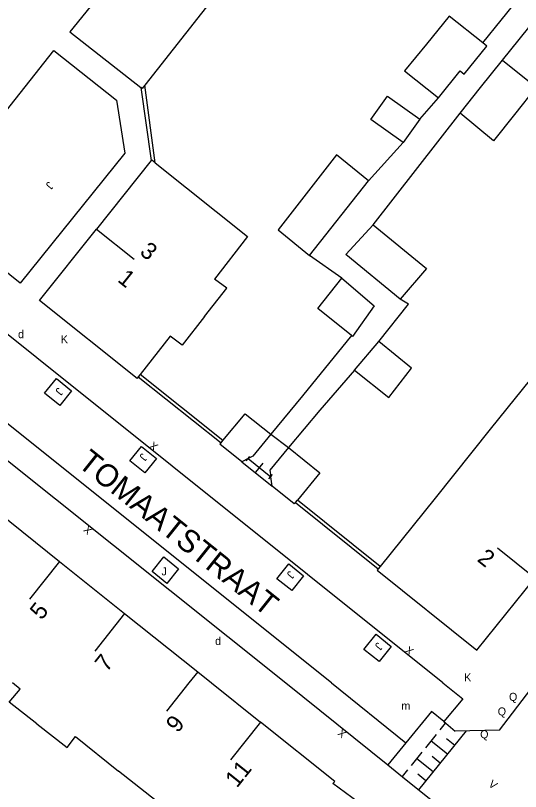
# Model space of a CAD drawing. Extents: x 134999 to 136502, y 457398 to 459002.
# Drawn here: x 135341.41 to 135372.94, y 457793.22 to 457841.67 of the extents above; entities that cross this region are included whole.
import ezdxf

# ---------------------------------------------------------------- set-up
doc = ezdxf.new("R2010")
doc.units = 0
for name, color, linetype in [('RI_DGTB_15', 7, 'Continuous'), ('RI_DGTB_23', 7, 'Continuous'), ('RI_DGTB_29', 7, 'Continuous'), ('RI_DGTB_30', 7, 'Continuous'), ('RI_DGTB_31', 7, 'Continuous'), ('RI_DGTB_35', 7, 'Continuous'), ('RI_DGTB_36', 7, 'Continuous'), ('RI_DGTB_37', 7, 'Continuous'), ('RI_DGTB_4', 7, 'Continuous'), ('RI_DGTB_43', 7, 'Continuous'), ('RI_DGTB_48', 7, 'Continuous'), ('RI_DGTB_5', 7, 'Continuous'), ('RI_DGTB_53', 7, 'Continuous'), ('RI_DGTB_54', 7, 'Continuous'), ('RI_DGTB_6', 7, 'Continuous'), ('RI_DGTB_7', 7, 'Continuous')]:
    doc.layers.add(name, color=color, linetype=linetype)

msp = doc.modelspace()

# ---------------------------------------------------------------- linework, layer by layer
at = {"layer": 'RI_DGTB_15'}
for p, q in [((135346.469, 457828.337), (135348.813, 457826.464)), ((135346.469, 457828.337), (135348.813, 457826.464)), ((135373.839, 457806.545), (135371.499, 457808.422)), ((135373.839, 457806.545), (135371.499, 457808.422)), ((135344.159, 457807.579), (135342.293, 457805.231)), ((135344.159, 457807.579), (135342.293, 457805.231)), ((135348.221, 457804.331), (135346.355, 457801.983)), ((135348.221, 457804.331), (135346.355, 457801.983)), ((135352.793, 457800.688), (135352.245, 457800)), ((135352.793, 457800.688), (135352.245, 457800)), ((135352.245, 457800), (135350.83, 457798.228)), ((135356.716, 457797.543), (135354.845, 457795.199))]:
    msp.add_line(p, q, dxfattribs=at)
at = {"layer": 'RI_DGTB_23'}
msp.add_line((135355.539, 457813.811), (135357.44, 457812.288), dxfattribs=at)
msp.add_line((135355.539, 457813.811), (135357.44, 457812.288), dxfattribs=at)
at = {"layer": 'RI_DGTB_31'}
for p, q in [((135367.931, 457797.059), (135368.267, 457797.475)), ((135366.595, 457793.329), (135369.565, 457797.005)), ((135367.035, 457795.95), (135367.707, 457796.782)), ((135368.386, 457795.546), (135367.371, 457796.366)), ((135368.834, 457796.1), (135368.327, 457796.51)), ((135366.139, 457794.84), (135366.811, 457795.672)), ((135367.49, 457794.436), (135366.475, 457795.256)), ((135367.938, 457794.991), (135367.431, 457795.401)), ((135365.579, 457794.147), (135365.915, 457794.563)), ((135367.042, 457793.882), (135366.535, 457794.292))]:
    msp.add_line(p, q, dxfattribs=at)
for points in [[(135343.226, 457818.083), (135343.963, 457819.005), (135344.915, 457818.244), (135344.178, 457817.322)], [(135343.226, 457818.083), (135343.963, 457819.005), (135344.915, 457818.244), (135344.178, 457817.322)], [(135348.555, 457813.858), (135349.273, 457814.757), (135350.209, 457814.009), (135349.491, 457813.11)], [(135348.555, 457813.858), (135349.273, 457814.757), (135350.209, 457814.009), (135349.491, 457813.11)], [(135349.941, 457806.955), (135350.665, 457807.862), (135351.595, 457807.119), (135350.871, 457806.212)], [(135349.941, 457806.955), (135350.665, 457807.862), (135351.595, 457807.119), (135350.871, 457806.212)], [(135357.731, 457806.505), (135358.474, 457807.435), (135359.403, 457806.692), (135358.66, 457805.762)], [(135357.731, 457806.505), (135358.474, 457807.435), (135359.403, 457806.692), (135358.66, 457805.762)], [(135363.166, 457802.093), (135363.922, 457803.038), (135364.867, 457802.282), (135364.111, 457801.337)], [(135363.166, 457802.093), (135363.922, 457803.038), (135364.867, 457802.282), (135364.111, 457801.337)]]:
    msp.add_lwpolyline(points, close=True, dxfattribs=at)
at = {"layer": 'RI_DGTB_4'}
for p, q in [((135354.061, 457843.14), (135349.485, 457837.321)), ((135349.889, 457832.616), (135346.469, 457828.337)), ((135349.889, 457832.616), (135346.469, 457828.337)), ((135351.065, 457821.651), (135349.2, 457819.255)), ((135351.065, 457821.651), (135349.2, 457819.255)), ((135349.2, 457819.255), (135349.081, 457819.102)), ((135349.2, 457819.255), (135349.081, 457819.102)), ((135339.674, 457811.167), (135344.161, 457807.581)), ((135339.674, 457811.167), (135344.161, 457807.581)), ((135344.161, 457807.581), (135348.224, 457804.334)), ((135344.161, 457807.581), (135348.224, 457804.334)), ((135348.224, 457804.334), (135352.79, 457800.685)), ((135348.224, 457804.334), (135352.79, 457800.685)), ((135352.79, 457800.685), (135353.647, 457800)), ((135352.79, 457800.685), (135353.647, 457800)), ((135353.647, 457800), (135356.718, 457797.546))]:
    msp.add_line(p, q, dxfattribs=at)
for points in [[(135349.697, 457846.698), (135344.809, 457840.663), (135349.233, 457837.181)], [(135349.485, 457837.321), (135349.321, 457837.112), (135349.233, 457837.181)], [(135350.134, 457832.475), (135349.916, 457832.649), (135349.889, 457832.616)], [(135350.134, 457832.475), (135349.916, 457832.649), (135349.889, 457832.616)], [(135350.134, 457832.475), (135355.903, 457827.871), (135353.839, 457825.218)], [(135350.134, 457832.475), (135355.903, 457827.871), (135353.839, 457825.218)], [(135349.081, 457819.102), (135349, 457818.998), (135342.907, 457823.881), (135346.469, 457828.337)], [(135349.081, 457819.102), (135349, 457818.998), (135342.907, 457823.881), (135346.469, 457828.337)], [(135363.986, 457807.032), (135370.226, 457802.041), (135373.837, 457806.546)], [(135363.986, 457807.032), (135370.226, 457802.041), (135373.837, 457806.546)], [(135361.5, 457788.617), (135363.351, 457790.897), (135363.198, 457792.262), (135361.222, 457793.718), (135361.349, 457793.845), (135356.718, 457797.546)]]:
    msp.add_lwpolyline(points, dxfattribs=at)
at = {"layer": 'RI_DGTB_48'}
for p, q in [((135355.822, 457813.865), (135356.048, 457814.147)), ((135355.822, 457813.865), (135356.048, 457814.147)), ((135355.935, 457814.006), (135357.348, 457812.874)), ((135355.935, 457814.006), (135357.348, 457812.874)), ((135355.935, 457814.006), (135357.348, 457812.874)), ((135355.935, 457814.006), (135357.348, 457812.874)), ((135356.415, 457813.157), (135356.868, 457813.723)), ((135356.415, 457813.157), (135356.868, 457813.723)), ((135357.235, 457812.733), (135357.461, 457813.015)), ((135357.235, 457812.733), (135357.461, 457813.015))]:
    msp.add_line(p, q, dxfattribs=at)
at = {"layer": 'RI_DGTB_5'}
for p, q in [((135374.492, 457820.127), (135371.05, 457815.836)), ((135374.492, 457820.127), (135371.05, 457815.836)), ((135371.05, 457815.836), (135367.606, 457811.544)), ((135371.05, 457815.836), (135367.606, 457811.544)), ((135367.606, 457811.544), (135364.177, 457807.27)), ((135367.606, 457811.544), (135364.177, 457807.27)), ((135364.177, 457807.27), (135364.06, 457807.125)), ((135364.177, 457807.27), (135364.06, 457807.125)), ((135364.06, 457807.125), (135363.986, 457807.032)), ((135364.06, 457807.125), (135363.986, 457807.032))]:
    msp.add_line(p, q, dxfattribs=at)
for points in [[(135353.218, 457822.882), (135354.612, 457824.65), (135353.839, 457825.218)], [(135353.218, 457822.882), (135354.612, 457824.65), (135353.839, 457825.218)], [(135353.218, 457822.882), (135351.81, 457821.098), (135351.065, 457821.651)], [(135353.218, 457822.882), (135351.81, 457821.098), (135351.065, 457821.651)], [(135342.748, 457797.444), (135341.015, 457798.796), (135341.708, 457799.616), (135341.228, 457800)], [(135342.748, 457797.444), (135344.634, 457795.972), (135345.162, 457796.645), (135347.85, 457794.495)], [(135351.238, 457790.679), (135349.64, 457791.9), (135350.187, 457792.626), (135347.85, 457794.495)]]:
    msp.add_lwpolyline(points, dxfattribs=at)
at = {"layer": 'RI_DGTB_53'}
msp.add_line((135361.142, 457800), (135365.792, 457796.264), dxfattribs=at)
msp.add_lwpolyline([(135361.149, 457800), (135340.114, 457816.81), (135338.999, 457815.415)], dxfattribs=at)
msp.add_lwpolyline([(135361.149, 457800), (135340.114, 457816.81), (135338.999, 457815.415)], dxfattribs=at)
at = {"layer": 'RI_DGTB_54'}
for p, q in [((135370.583, 457839.961), (135374.666, 457845.018)), ((135350.134, 457832.475), (135349.485, 457837.321)), ((135349.233, 457837.181), (135349.889, 457832.616)), ((135366.666, 457835.21), (135367.833, 457836.534)), ((135366.666, 457835.21), (135367.833, 457836.534)), ((135363.745, 457828.606), (135369.176, 457835.585)), ((135363.745, 457828.606), (135369.176, 457835.585)), ((135363.457, 457831.341), (135365.615, 457833.734)), ((135363.457, 457831.341), (135365.615, 457833.734)), ((135361.783, 457825.262), (135359.765, 457826.686)), ((135361.783, 457825.262), (135359.765, 457826.686)), ((135349.081, 457819.102), (135354.247, 457814.997)), ((135349.081, 457819.102), (135354.247, 457814.997)), ((135354.354, 457815.126), (135349.2, 457819.255)), ((135354.354, 457815.126), (135349.2, 457819.255)), ((135338.999, 457815.415), (135358.291, 457800)), ((135338.999, 457815.415), (135358.291, 457800)), ((135358.899, 457811.267), (135364.06, 457807.125)), ((135358.899, 457811.267), (135364.06, 457807.125)), ((135364.177, 457807.27), (135359.013, 457811.407)), ((135364.177, 457807.27), (135359.013, 457811.407)), ((135358.291, 457800), (135364.663, 457794.881)), ((135371.639, 457797.057), (135373.589, 457799.605)), ((135371.639, 457797.057), (135368.863, 457796.988)), ((135365.792, 457796.264), (135364.663, 457794.881))]:
    msp.add_line(p, q, dxfattribs=at)
for points in [[(135371.83, 457838.886), (135373.981, 457841.574)], [(135336.849, 457828.858), (135336.942, 457830.815), (135343.802, 457839.481), (135347.711, 457836.395), (135348.249, 457833.08), (135341.698, 457824.965), (135336.849, 457828.858)], [(135368.102, 457800), (135334.271, 457827.065), (135333.852, 457826.605)], [(135368.102, 457800), (135334.271, 457827.065), (135333.852, 457826.605)], [(135364.091, 457821.323), (135365.951, 457823.641), (135365.439, 457823.965)], [(135364.091, 457821.323), (135365.951, 457823.641), (135365.439, 457823.965)], [(135362.387, 457821.696), (135359.339, 457817.927), (135357.357, 457815.526)], [(135362.387, 457821.696), (135359.339, 457817.927), (135357.357, 457815.526)], [(135362.588, 457819.537), (135360.415, 457817.034), (135358.454, 457814.691)], [(135362.588, 457819.537), (135360.415, 457817.034), (135358.454, 457814.691)], [(135368.102, 457800), (135369.335, 457799.014), (135368.161, 457797.582)], [(135368.161, 457797.582), (135367.387, 457798.215), (135365.792, 457796.264)], [(135368.161, 457797.582), (135368.279, 457797.482)], [(135368.279, 457797.482), (135368.863, 457796.988)], [(135364.663, 457794.881), (135365.582, 457794.143)], [(135365.582, 457794.143), (135372.361, 457788.697)]]:
    msp.add_lwpolyline(points, dxfattribs=at)
at = {"layer": 'RI_DGTB_6'}
for p, q in [((135371.83, 457838.886), (135373.923, 457837.202)), ((135359.765, 457826.686), (135363.457, 457831.341)), ((135359.765, 457826.686), (135363.457, 457831.341)), ((135362.588, 457819.537), (135364.091, 457821.323)), ((135362.588, 457819.537), (135364.091, 457821.323)), ((135354.247, 457814.997), (135354.354, 457815.126)), ((135354.247, 457814.997), (135354.354, 457815.126)), ((135358.899, 457811.267), (135359.013, 457811.407)), ((135358.899, 457811.267), (135359.013, 457811.407))]:
    msp.add_line(p, q, dxfattribs=at)
for points in [[(135368.5, 457841.634), (135367.078, 457839.894)], [(135370.583, 457839.961), (135368.5, 457841.634)], [(135367.078, 457839.894), (135365.708, 457838.217), (135367.833, 457836.534)], [(135369.173, 457838.214), (135369.43, 457838.008), (135370.837, 457839.757), (135370.583, 457839.961)], [(135370.457, 457837.182), (135371.83, 457838.886)], [(135367.833, 457836.534), (135369.173, 457838.214)], [(135369.176, 457835.585), (135370.457, 457837.182)], [(135373.923, 457837.202), (135372.563, 457835.494)], [(135365.615, 457833.734), (135363.598, 457835.171), (135364.65, 457836.647)], [(135365.615, 457833.734), (135363.598, 457835.171), (135364.65, 457836.647)], [(135364.65, 457836.647), (135366.666, 457835.21)], [(135364.65, 457836.647), (135366.666, 457835.21)], [(135372.563, 457835.494), (135371.256, 457833.853), (135369.176, 457835.585)], [(135372.563, 457835.494), (135371.256, 457833.853), (135369.176, 457835.585)], [(135366.666, 457835.21), (135365.615, 457833.734)], [(135366.666, 457835.21), (135365.615, 457833.734)], [(135363.457, 457831.341), (135361.458, 457832.979), (135357.816, 457828.284), (135359.765, 457826.686)], [(135363.457, 457831.341), (135361.458, 457832.979), (135357.816, 457828.284), (135359.765, 457826.686)], [(135365.439, 457823.965), (135362.042, 457826.742), (135363.745, 457828.606)], [(135365.439, 457823.965), (135362.042, 457826.742), (135363.745, 457828.606)], [(135363.745, 457828.606), (135367.081, 457825.879), (135365.439, 457823.965)], [(135363.745, 457828.606), (135367.081, 457825.879), (135365.439, 457823.965)], [(135362.387, 457821.696), (135360.287, 457823.386), (135361.783, 457825.262)], [(135362.387, 457821.696), (135360.287, 457823.386), (135361.783, 457825.262)], [(135361.783, 457825.262), (135363.804, 457823.545), (135362.464, 457821.635), (135362.387, 457821.696)], [(135361.783, 457825.262), (135363.804, 457823.545), (135362.464, 457821.635), (135362.387, 457821.696)], [(135362.588, 457819.537), (135364.725, 457817.817), (135366.146, 457819.648), (135364.091, 457821.323)], [(135362.588, 457819.537), (135364.725, 457817.817), (135366.146, 457819.648), (135364.091, 457821.323)], [(135354.354, 457815.126), (135355.748, 457816.807), (135357.357, 457815.526)], [(135354.354, 457815.126), (135355.748, 457816.807), (135357.357, 457815.526)], [(135357.357, 457815.526), (135356.233, 457814.152), (135355.935, 457814.006)], [(135357.357, 457815.526), (135356.233, 457814.152), (135355.935, 457814.006)], [(135355.539, 457813.811), (135354.177, 457814.913), (135354.247, 457814.997)], [(135355.539, 457813.811), (135354.177, 457814.913), (135354.247, 457814.997)], [(135358.454, 457814.691), (135357.285, 457813.273), (135357.348, 457812.874)], [(135358.454, 457814.691), (135357.285, 457813.273), (135357.348, 457812.874)], [(135358.454, 457814.691), (135360.419, 457813.123), (135359.013, 457811.407)], [(135358.454, 457814.691), (135360.419, 457813.123), (135359.013, 457811.407)], [(135355.935, 457814.006), (135355.539, 457813.811)], [(135355.935, 457814.006), (135355.539, 457813.811)], [(135357.44, 457812.288), (135357.348, 457812.874)], [(135357.44, 457812.288), (135357.348, 457812.874)], [(135358.899, 457811.267), (135358.822, 457811.173), (135357.44, 457812.288)], [(135358.899, 457811.267), (135358.822, 457811.173), (135357.44, 457812.288)]]:
    msp.add_lwpolyline(points, dxfattribs=at)
at = {"layer": 'RI_DGTB_7'}
for points in [[(135357.357, 457815.526), (135358.454, 457814.691)], [(135357.357, 457815.526), (135358.454, 457814.691)], [(135355.539, 457813.811), (135357.44, 457812.288)], [(135355.539, 457813.811), (135357.44, 457812.288)]]:
    msp.add_lwpolyline(points, dxfattribs=at)

# ---------------------------------------------------------------- texts
at = {"layer": 'RI_DGTB_29'}
for height, p in [(0.499, (135341.57, 457821.525)), (0.499, (135341.57, 457821.525)), (0.5, (135353.873, 457802.367)), (0.5, (135353.873, 457802.367))]:
    msp.add_text('d', height=height, dxfattribs=at).set_placement(p)
at = {"layer": 'RI_DGTB_30'}
for p in [(135344.241, 457821.21), (135344.241, 457821.21), (135369.425, 457800.096), (135369.425, 457800.096)]:
    msp.add_text('K', height=0.5, dxfattribs=at).set_placement(p)
for s, rotation, p in [('X', 321.3711, (135349.703, 457814.72)), ('X', 321.3711, (135349.703, 457814.72)), ('X', 136.3013, (135346.273, 457809.576)), ('X', 136.3013, (135346.273, 457809.576)), ('X', 321.3305, (135365.665, 457801.95)), ('X', 321.3305, (135365.665, 457801.95)), ('X', 141.2553, (135362.133, 457796.904)), ('V', 321.3996, (135370.898, 457793.594))]:
    msp.add_text(s, height=0.499, rotation=rotation, dxfattribs=at).set_placement(p)
at = {"layer": 'RI_DGTB_31'}
for height, rotation, p in [(0.499, 231.3305, (135343.464, 457831.338)), (0.499, 231.3305, (135343.464, 457831.338)), (0.5, 231.34, (135344.065, 457818.477)), (0.5, 231.34, (135344.065, 457818.477)), (0.5, 231.34, (135349.315, 457814.379)), (0.5, 231.34, (135349.315, 457814.379)), (0.5, 231.34, (135358.512, 457807.034)), (0.5, 231.34, (135358.512, 457807.034)), (0.5, 231.34, (135364.017, 457802.566)), (0.5, 231.34, (135364.017, 457802.566))]:
    msp.add_text('J', height=height, rotation=rotation, dxfattribs=at).set_placement(p)
for s, p in [('J', (135350.531, 457806.714)), ('J', (135350.531, 457806.714)), ('Q', (135372.225, 457798.878)), ('Q', (135371.524, 457797.966)), ('Q', (135370.425, 457796.54))]:
    msp.add_text(s, height=0.5, dxfattribs=at).set_placement(p)
at = {"layer": 'RI_DGTB_35'}
for s, rotation, p in [('1', 321.3671, (135347.726, 457825.103)), ('1', 321.3671, (135347.726, 457825.103)), ('2', 321.2844, (135370.18, 457807.648)), ('2', 321.2844, (135370.18, 457807.648))]:
    msp.add_text(s, height=1.054, rotation=rotation, dxfattribs=at).set_placement(p)
at = {"layer": 'RI_DGTB_36'}
for s, rotation, p in [('3', 321.3581, (135349.108, 457826.807)), ('3', 321.3581, (135349.108, 457826.807)), ('5', 51.5234, (135343.042, 457803.875)), ('5', 51.5234, (135343.042, 457803.875)), ('7', 51.5234, (135347.109, 457800.631)), ('7', 51.5234, (135347.109, 457800.631)), ('9', 51.3994, (135351.54, 457796.825)), ('11', 51.3994, (135355.24, 457793.399))]:
    msp.add_text(s, height=1.054, rotation=rotation, dxfattribs=at).set_placement(p)
at = {"layer": 'RI_DGTB_37'}
msp.add_text('TOMAATSTRAAT', height=1.4, rotation=321.3739, dxfattribs=at).set_placement((135345.229, 457813.575))
msp.add_text('TOMAATSTRAAT', height=1.4, rotation=321.3739, dxfattribs=at).set_placement((135345.229, 457813.575))
at = {"layer": 'RI_DGTB_43'}
msp.add_text('m', height=0.5, dxfattribs=at).set_placement((135365.509, 457798.324))

doc.saveas('drawing.dxf')
